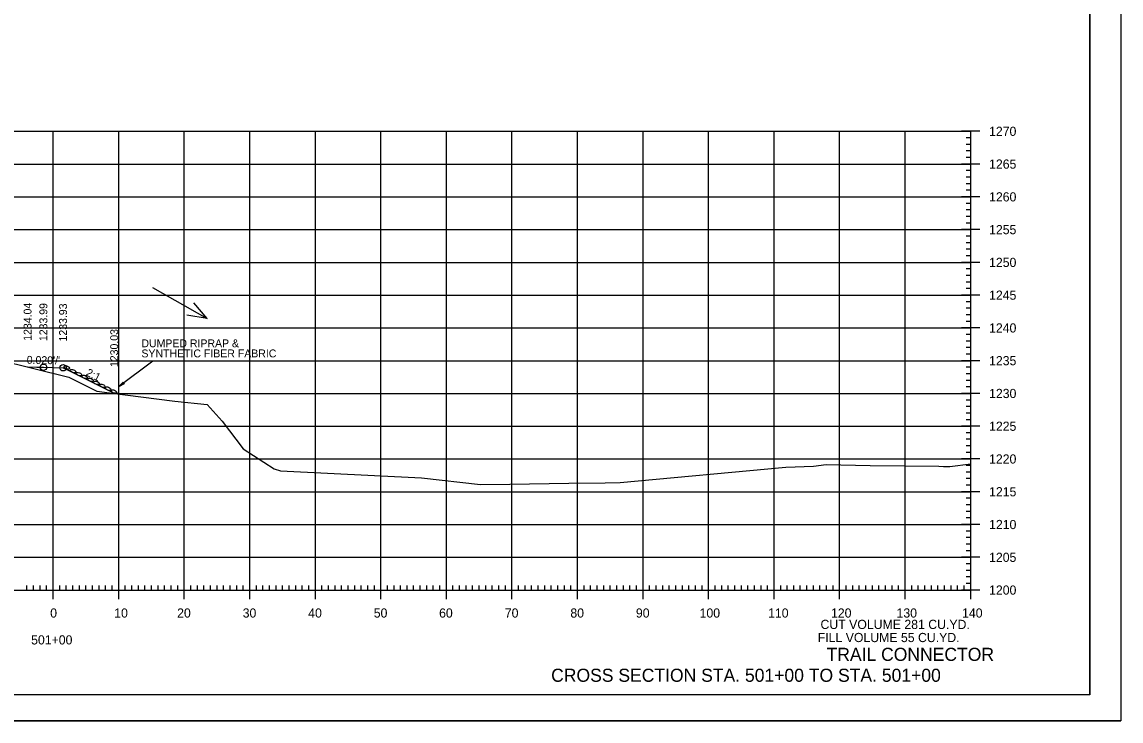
# Model space of a CAD drawing. Extents: x 1406028 to 1412453, y 321733 to 325986.
# Drawn here: x 1412285.5 to 1412453.2, y 322065 to 322171.7 of the extents above; entities that cross this region are included whole.
import ezdxf

# ---------------------------------------------------------------- set-up
doc = ezdxf.new("R2010")
doc.units = 0
for name, color, linetype in [('R_Axis', 7, 'Continuous'), ('R_Axis Annot', 7, 'Continuous'), ('R_Border', 7, 'Continuous'), ('R_Draft', 7, 'Continuous'), ('R_Exist Surface', 7, 'Continuous'), ('R_Fin Surface', 7, 'Continuous'), ('R_Fin Surface Annot', 7, 'Continuous'), ('R_Grid', 7, 'Continuous'), ('R_No Plot', 7, 'Continuous'), ('R_Water Annot', 7, 'Continuous')]:
    doc.layers.add(name, color=color, linetype=linetype)

msp = doc.modelspace()

# ---------------------------------------------------------------- linework, layer by layer
at = {"layer": 'R_Axis'}
for p, q in [((1412431.63, 322155.01), (1412428.83, 322155.01)), ((1412430.23, 322085.01), (1412430.23, 322155.01)), ((1412430.23, 322154.01), (1412429.53, 322154.01)), ((1412430.23, 322153.01), (1412429.53, 322153.01)), ((1412430.23, 322152.01), (1412429.53, 322152.01)), ((1412431.63, 322150.01), (1412428.83, 322150.01)), ((1412430.23, 322151.01), (1412429.53, 322151.01)), ((1412430.23, 322149.01), (1412429.53, 322149.01)), ((1412430.23, 322148.01), (1412429.53, 322148.01)), ((1412430.23, 322147.01), (1412429.53, 322147.01)), ((1412431.63, 322145.01), (1412428.83, 322145.01)), ((1412430.23, 322146.01), (1412429.53, 322146.01)), ((1412430.23, 322144.01), (1412429.53, 322144.01)), ((1412430.23, 322143.01), (1412429.53, 322143.01)), ((1412430.23, 322142.01), (1412429.53, 322142.01)), ((1412431.63, 322140.01), (1412428.83, 322140.01)), ((1412430.23, 322141.01), (1412429.53, 322141.01)), ((1412430.23, 322139.01), (1412429.53, 322139.01)), ((1412430.23, 322138.01), (1412429.53, 322138.01)), ((1412430.23, 322137.01), (1412429.53, 322137.01)), ((1412431.63, 322135.01), (1412428.83, 322135.01)), ((1412430.23, 322136.01), (1412429.53, 322136.01)), ((1412430.23, 322134.01), (1412429.53, 322134.01)), ((1412430.23, 322133.01), (1412429.53, 322133.01)), ((1412430.23, 322132.01), (1412429.53, 322132.01)), ((1412431.63, 322130.01), (1412428.83, 322130.01)), ((1412430.23, 322131.01), (1412429.53, 322131.01)), ((1412430.23, 322129.01), (1412429.53, 322129.01)), ((1412430.23, 322128.01), (1412429.53, 322128.01)), ((1412430.23, 322127.01), (1412429.53, 322127.01)), ((1412431.63, 322125.01), (1412428.83, 322125.01)), ((1412430.23, 322126.01), (1412429.53, 322126.01)), ((1412430.23, 322124.01), (1412429.53, 322124.01)), ((1412430.23, 322123.01), (1412429.53, 322123.01)), ((1412430.23, 322122.01), (1412429.53, 322122.01)), ((1412431.63, 322120.01), (1412428.83, 322120.01)), ((1412430.23, 322121.01), (1412429.53, 322121.01)), ((1412430.23, 322119.01), (1412429.53, 322119.01)), ((1412430.23, 322118.01), (1412429.53, 322118.01)), ((1412430.23, 322117.01), (1412429.53, 322117.01)), ((1412431.63, 322115.01), (1412428.83, 322115.01)), ((1412430.23, 322116.01), (1412429.53, 322116.01)), ((1412430.23, 322114.01), (1412429.53, 322114.01)), ((1412430.23, 322113.01), (1412429.53, 322113.01)), ((1412430.23, 322112.01), (1412429.53, 322112.01)), ((1412430.23, 322111.01), (1412429.53, 322111.01)), ((1412431.63, 322110.01), (1412428.83, 322110.01)), ((1412430.23, 322109.01), (1412429.53, 322109.01)), ((1412430.23, 322108.01), (1412429.53, 322108.01)), ((1412430.23, 322107.01), (1412429.53, 322107.01)), ((1412430.23, 322106.01), (1412429.53, 322106.01)), ((1412431.63, 322105.01), (1412428.83, 322105.01)), ((1412430.23, 322104.01), (1412429.53, 322104.01)), ((1412430.23, 322103.01), (1412429.53, 322103.01)), ((1412430.23, 322102.01), (1412429.53, 322102.01)), ((1412430.23, 322101.01), (1412429.53, 322101.01)), ((1412431.63, 322100.01), (1412428.83, 322100.01)), ((1412430.23, 322099.01), (1412429.53, 322099.01)), ((1412430.23, 322098.01), (1412429.53, 322098.01)), ((1412430.23, 322097.01), (1412429.53, 322097.01)), ((1412430.23, 322096.01), (1412429.53, 322096.01)), ((1412431.63, 322095.01), (1412428.83, 322095.01)), ((1412430.23, 322094.01), (1412429.53, 322094.01)), ((1412430.23, 322093.01), (1412429.53, 322093.01)), ((1412430.23, 322092.01), (1412429.53, 322092.01)), ((1412430.23, 322091.01), (1412429.53, 322091.01)), ((1412431.63, 322090.01), (1412428.83, 322090.01)), ((1412430.23, 322089.01), (1412429.53, 322089.01)), ((1412430.23, 322088.01), (1412429.53, 322088.01)), ((1412290.23, 322083.61), (1412290.23, 322086.41)), ((1412300.23, 322083.61), (1412300.23, 322086.41)), ((1412310.23, 322083.61), (1412310.23, 322086.41)), ((1412320.23, 322083.61), (1412320.23, 322086.41)), ((1412330.23, 322083.61), (1412330.23, 322086.41)), ((1412340.23, 322083.61), (1412340.23, 322086.41)), ((1412350.23, 322083.61), (1412350.23, 322086.41)), ((1412360.23, 322083.61), (1412360.23, 322086.41)), ((1412370.23, 322083.61), (1412370.23, 322086.41)), ((1412380.23, 322083.61), (1412380.23, 322086.41)), ((1412390.23, 322083.61), (1412390.23, 322086.41)), ((1412400.23, 322083.61), (1412400.23, 322086.41)), ((1412410.23, 322083.61), (1412410.23, 322086.41)), ((1412420.23, 322083.61), (1412420.23, 322086.41)), ((1412430.23, 322087.01), (1412429.53, 322087.01)), ((1412430.23, 322086.01), (1412429.53, 322086.01)), ((1412430.23, 322083.61), (1412430.23, 322086.41)), ((1412150.23, 322085.01), (1412430.23, 322085.01)), ((1412286.23, 322085.01), (1412286.23, 322085.71)), ((1412287.23, 322085.01), (1412287.23, 322085.71)), ((1412288.23, 322085.01), (1412288.23, 322085.71)), ((1412289.23, 322085.01), (1412289.23, 322085.71)), ((1412291.23, 322085.01), (1412291.23, 322085.71)), ((1412292.23, 322085.01), (1412292.23, 322085.71)), ((1412293.23, 322085.01), (1412293.23, 322085.71)), ((1412294.23, 322085.01), (1412294.23, 322085.71)), ((1412295.23, 322085.01), (1412295.23, 322085.71)), ((1412296.23, 322085.01), (1412296.23, 322085.71)), ((1412297.23, 322085.01), (1412297.23, 322085.71)), ((1412298.23, 322085.01), (1412298.23, 322085.71)), ((1412299.23, 322085.01), (1412299.23, 322085.71)), ((1412301.23, 322085.01), (1412301.23, 322085.71)), ((1412302.23, 322085.01), (1412302.23, 322085.71)), ((1412303.23, 322085.01), (1412303.23, 322085.71)), ((1412304.23, 322085.01), (1412304.23, 322085.71)), ((1412305.23, 322085.01), (1412305.23, 322085.71)), ((1412306.23, 322085.01), (1412306.23, 322085.71)), ((1412307.23, 322085.01), (1412307.23, 322085.71)), ((1412308.23, 322085.01), (1412308.23, 322085.71)), ((1412309.23, 322085.01), (1412309.23, 322085.71)), ((1412311.23, 322085.01), (1412311.23, 322085.71)), ((1412312.23, 322085.01), (1412312.23, 322085.71)), ((1412313.23, 322085.01), (1412313.23, 322085.71)), ((1412314.23, 322085.01), (1412314.23, 322085.71)), ((1412315.23, 322085.01), (1412315.23, 322085.71)), ((1412316.23, 322085.01), (1412316.23, 322085.71)), ((1412317.23, 322085.01), (1412317.23, 322085.71)), ((1412318.23, 322085.01), (1412318.23, 322085.71)), ((1412319.23, 322085.01), (1412319.23, 322085.71)), ((1412321.23, 322085.01), (1412321.23, 322085.71)), ((1412322.23, 322085.01), (1412322.23, 322085.71)), ((1412323.23, 322085.01), (1412323.23, 322085.71)), ((1412324.23, 322085.01), (1412324.23, 322085.71)), ((1412325.23, 322085.01), (1412325.23, 322085.71)), ((1412326.23, 322085.01), (1412326.23, 322085.71)), ((1412327.23, 322085.01), (1412327.23, 322085.71)), ((1412328.23, 322085.01), (1412328.23, 322085.71)), ((1412329.23, 322085.01), (1412329.23, 322085.71)), ((1412331.23, 322085.01), (1412331.23, 322085.71)), ((1412332.23, 322085.01), (1412332.23, 322085.71)), ((1412333.23, 322085.01), (1412333.23, 322085.71)), ((1412334.23, 322085.01), (1412334.23, 322085.71)), ((1412335.23, 322085.01), (1412335.23, 322085.71)), ((1412336.23, 322085.01), (1412336.23, 322085.71)), ((1412337.23, 322085.01), (1412337.23, 322085.71)), ((1412338.23, 322085.01), (1412338.23, 322085.71)), ((1412339.23, 322085.01), (1412339.23, 322085.71)), ((1412341.23, 322085.01), (1412341.23, 322085.71)), ((1412342.23, 322085.01), (1412342.23, 322085.71)), ((1412343.23, 322085.01), (1412343.23, 322085.71)), ((1412344.23, 322085.01), (1412344.23, 322085.71)), ((1412345.23, 322085.01), (1412345.23, 322085.71)), ((1412346.23, 322085.01), (1412346.23, 322085.71)), ((1412347.23, 322085.01), (1412347.23, 322085.71)), ((1412348.23, 322085.01), (1412348.23, 322085.71)), ((1412349.23, 322085.01), (1412349.23, 322085.71)), ((1412351.23, 322085.01), (1412351.23, 322085.71)), ((1412352.23, 322085.01), (1412352.23, 322085.71)), ((1412353.23, 322085.01), (1412353.23, 322085.71)), ((1412354.23, 322085.01), (1412354.23, 322085.71)), ((1412355.23, 322085.01), (1412355.23, 322085.71)), ((1412356.23, 322085.01), (1412356.23, 322085.71)), ((1412357.23, 322085.01), (1412357.23, 322085.71)), ((1412358.23, 322085.01), (1412358.23, 322085.71)), ((1412359.23, 322085.01), (1412359.23, 322085.71)), ((1412361.23, 322085.01), (1412361.23, 322085.71)), ((1412362.23, 322085.01), (1412362.23, 322085.71)), ((1412363.23, 322085.01), (1412363.23, 322085.71)), ((1412364.23, 322085.01), (1412364.23, 322085.71)), ((1412365.23, 322085.01), (1412365.23, 322085.71)), ((1412366.23, 322085.01), (1412366.23, 322085.71)), ((1412367.23, 322085.01), (1412367.23, 322085.71)), ((1412368.23, 322085.01), (1412368.23, 322085.71)), ((1412369.23, 322085.01), (1412369.23, 322085.71)), ((1412371.23, 322085.01), (1412371.23, 322085.71)), ((1412372.23, 322085.01), (1412372.23, 322085.71)), ((1412373.23, 322085.01), (1412373.23, 322085.71)), ((1412374.23, 322085.01), (1412374.23, 322085.71)), ((1412375.23, 322085.01), (1412375.23, 322085.71)), ((1412376.23, 322085.01), (1412376.23, 322085.71)), ((1412377.23, 322085.01), (1412377.23, 322085.71)), ((1412378.23, 322085.01), (1412378.23, 322085.71)), ((1412379.23, 322085.01), (1412379.23, 322085.71)), ((1412381.23, 322085.01), (1412381.23, 322085.71)), ((1412382.23, 322085.01), (1412382.23, 322085.71)), ((1412383.23, 322085.01), (1412383.23, 322085.71)), ((1412384.23, 322085.01), (1412384.23, 322085.71)), ((1412385.23, 322085.01), (1412385.23, 322085.71)), ((1412386.23, 322085.01), (1412386.23, 322085.71)), ((1412387.23, 322085.01), (1412387.23, 322085.71)), ((1412388.23, 322085.01), (1412388.23, 322085.71)), ((1412389.23, 322085.01), (1412389.23, 322085.71)), ((1412391.23, 322085.01), (1412391.23, 322085.71)), ((1412392.23, 322085.01), (1412392.23, 322085.71)), ((1412393.23, 322085.01), (1412393.23, 322085.71)), ((1412394.23, 322085.01), (1412394.23, 322085.71)), ((1412395.23, 322085.01), (1412395.23, 322085.71)), ((1412396.23, 322085.01), (1412396.23, 322085.71)), ((1412397.23, 322085.01), (1412397.23, 322085.71)), ((1412398.23, 322085.01), (1412398.23, 322085.71)), ((1412399.23, 322085.01), (1412399.23, 322085.71)), ((1412401.23, 322085.01), (1412401.23, 322085.71)), ((1412402.23, 322085.01), (1412402.23, 322085.71)), ((1412403.23, 322085.01), (1412403.23, 322085.71)), ((1412404.23, 322085.01), (1412404.23, 322085.71)), ((1412405.23, 322085.01), (1412405.23, 322085.71)), ((1412406.23, 322085.01), (1412406.23, 322085.71)), ((1412407.23, 322085.01), (1412407.23, 322085.71)), ((1412408.23, 322085.01), (1412408.23, 322085.71)), ((1412409.23, 322085.01), (1412409.23, 322085.71)), ((1412411.23, 322085.01), (1412411.23, 322085.71)), ((1412412.23, 322085.01), (1412412.23, 322085.71)), ((1412413.23, 322085.01), (1412413.23, 322085.71)), ((1412414.23, 322085.01), (1412414.23, 322085.71)), ((1412415.23, 322085.01), (1412415.23, 322085.71)), ((1412416.23, 322085.01), (1412416.23, 322085.71)), ((1412417.23, 322085.01), (1412417.23, 322085.71)), ((1412418.23, 322085.01), (1412418.23, 322085.71)), ((1412419.23, 322085.01), (1412419.23, 322085.71)), ((1412421.23, 322085.01), (1412421.23, 322085.71)), ((1412422.23, 322085.01), (1412422.23, 322085.71)), ((1412423.23, 322085.01), (1412423.23, 322085.71)), ((1412424.23, 322085.01), (1412424.23, 322085.71)), ((1412425.23, 322085.01), (1412425.23, 322085.71)), ((1412426.23, 322085.01), (1412426.23, 322085.71)), ((1412427.23, 322085.01), (1412427.23, 322085.71)), ((1412428.23, 322085.01), (1412428.23, 322085.71)), ((1412431.63, 322085.01), (1412428.83, 322085.01)), ((1412429.23, 322085.01), (1412429.23, 322085.71))]:
    msp.add_line(p, q, dxfattribs=at)
at = {"layer": 'R_Border'}
for q in [(1412448.41, 322274.47), (1412132.23, 322069.01)]:
    msp.add_line((1412448.41, 322069.01), q, dxfattribs=at)
at = {"layer": 'R_Draft'}
for p, q in [((1412305.41, 322119.94), (1412300.18, 322116.02)), ((1412300.89, 322116.74), (1412300.18, 322116.02)), ((1412301.07, 322116.5), (1412300.18, 322116.02)), ((1412300.9, 322116.72), (1412300.31, 322116.12)), ((1412301.05, 322116.52), (1412300.31, 322116.12)), ((1412300.92, 322116.7), (1412300.45, 322116.22)), ((1412301.04, 322116.54), (1412300.45, 322116.22)), ((1412300.93, 322116.68), (1412300.58, 322116.32)), ((1412301.02, 322116.56), (1412300.58, 322116.32)), ((1412300.95, 322116.66), (1412300.72, 322116.42)), ((1412301.01, 322116.58), (1412300.72, 322116.42)), ((1412300.97, 322116.64), (1412300.85, 322116.52)), ((1412300.99, 322116.6), (1412300.85, 322116.52)), ((1412300.89, 322116.74), (1412301.07, 322116.5))]:
    msp.add_line(p, q, dxfattribs=at)
for centre in [(1412292.32, 322118.96), (1412293.25, 322118.42), (1412294.14, 322117.97), (1412295.04, 322117.53), (1412295.93, 322117.08), (1412296.83, 322116.63), (1412297.72, 322116.19), (1412298.61, 322115.74), (1412299.51, 322115.29)]:
    msp.add_ellipse(centre, major_axis=(0.409, -0.156), ratio=0.517889, dxfattribs=at)
at = {"layer": 'R_Exist Surface'}
msp.add_lwpolyline([(1412281.68, 322120.19), (1412292.6, 322117.5), (1412296.88, 322115.35), (1412298.81, 322115.13), (1412308.77, 322113.85), (1412313.72, 322113.35), (1412316, 322110.76), (1412319.21, 322106.56), (1412323.97, 322103.5), (1412324.89, 322103.22), (1412346.45, 322102.11), (1412355.44, 322101.1), (1412359.88, 322101.16), (1412368.91, 322101.31), (1412374.44, 322101.39), (1412376.73, 322101.43), (1412402.01, 322103.77), (1412406.24, 322103.91), (1412408.15, 322104.16), (1412414.88, 322104.01), (1412425.34, 322103.9), (1412426.1, 322103.84), (1412427.04, 322103.88), (1412430.23, 322104.27)], dxfattribs=at)
at = {"layer": 'R_Fin Surface'}
msp.add_lwpolyline([(1412286.32, 322119.05), (1412287.73, 322119.02), (1412288.73, 322119), (1412291.73, 322118.94), (1412292.73, 322118.44), (1412299.53, 322115.04)], dxfattribs=at)
at = {"layer": 'R_Grid'}
for p, q in [((1412150.23, 322155.01), (1412430.23, 322155.01)), ((1412290.23, 322085.01), (1412290.23, 322155.01)), ((1412300.23, 322085.01), (1412300.23, 322155.01)), ((1412310.23, 322085.01), (1412310.23, 322155.01)), ((1412320.23, 322085.01), (1412320.23, 322155.01)), ((1412330.23, 322085.01), (1412330.23, 322155.01)), ((1412340.23, 322085.01), (1412340.23, 322155.01)), ((1412350.23, 322085.01), (1412350.23, 322155.01)), ((1412360.23, 322085.01), (1412360.23, 322155.01)), ((1412370.23, 322085.01), (1412370.23, 322155.01)), ((1412380.23, 322085.01), (1412380.23, 322155.01)), ((1412390.23, 322085.01), (1412390.23, 322155.01)), ((1412400.23, 322085.01), (1412400.23, 322155.01)), ((1412410.23, 322085.01), (1412410.23, 322155.01)), ((1412420.23, 322085.01), (1412420.23, 322155.01)), ((1412430.23, 322085.01), (1412430.23, 322155.01)), ((1412150.23, 322150.01), (1412430.23, 322150.01)), ((1412150.23, 322145.01), (1412430.23, 322145.01)), ((1412150.23, 322140.01), (1412430.23, 322140.01)), ((1412150.23, 322135.01), (1412430.23, 322135.01)), ((1412150.23, 322130.01), (1412430.23, 322130.01)), ((1412150.23, 322125.01), (1412430.23, 322125.01)), ((1412150.23, 322120.01), (1412430.23, 322120.01)), ((1412150.23, 322115.01), (1412430.23, 322115.01)), ((1412150.23, 322110.01), (1412430.23, 322110.01)), ((1412150.23, 322105.01), (1412430.23, 322105.01)), ((1412150.23, 322100.01), (1412430.23, 322100.01)), ((1412150.23, 322095.01), (1412430.23, 322095.01)), ((1412150.23, 322090.01), (1412430.23, 322090.01)), ((1412150.23, 322085.01), (1412430.23, 322085.01))]:
    msp.add_line(p, q, dxfattribs=at)
at = {"layer": 'R_No Plot'}
msp.add_line((1412119.83, 322065.03), (1412453.16, 322065.03), dxfattribs=at)
for points in [[(1412119.82, 322278.36), (1412453.16, 322278.36), (1412453.16, 322065.03), (1412119.82, 322065.03)], [(1412366.15, 322274.47), (1412385.77, 322274.47), (1412385.77, 322264.59), (1412401.88, 322264.59), (1412425.08, 322264.59), (1412425.2, 322236.43), (1412448.41, 322236.43), (1412448.41, 322069.01), (1412132.23, 322069.01), (1412132.23, 322274.47)]]:
    msp.add_lwpolyline(points, close=True, dxfattribs=at)
for centre in [(1412288.73, 322119), (1412291.73, 322118.94)]:
    msp.add_circle(centre, 0.5, dxfattribs=at)
at = {"layer": 'R_Water Annot'}
for p, q in [((1412305.39, 322131.2), (1412313.71, 322126.46)), ((1412313.71, 322126.46), (1412311.7, 322128.84)), ((1412313.71, 322126.46), (1412310.64, 322126.98))]:
    msp.add_line(p, q, dxfattribs=at)

# ---------------------------------------------------------------- texts
at = {"layer": 'R_Axis Annot'}
for s, p in [('1270', (1412433.03, 322154.31)), ('1265', (1412433.03, 322149.31)), ('1260', (1412433.03, 322144.31)), ('1255', (1412433.03, 322139.31)), ('1250', (1412433.03, 322134.31)), ('1245', (1412433.03, 322129.31)), ('1240', (1412433.03, 322124.31)), ('1235', (1412433.03, 322119.31)), ('1230', (1412433.03, 322114.31)), ('1225', (1412433.03, 322109.31)), ('1220', (1412433.03, 322104.31)), ('1215', (1412433.03, 322099.31)), ('1210', (1412433.03, 322094.31)), ('1205', (1412433.03, 322089.31)), ('1200', (1412433.03, 322084.31)), ('0', (1412289.77, 322080.81)), ('10', (1412299.54, 322080.81)), ('20', (1412309.14, 322080.81)), ('30', (1412319.14, 322080.81)), ('40', (1412329.14, 322080.81)), ('50', (1412339.14, 322080.81)), ('60', (1412349.11, 322080.81)), ('70', (1412359.14, 322080.81)), ('80', (1412369.14, 322080.81)), ('90', (1412379.14, 322080.81)), ('100', (1412388.86, 322080.81)), ('110', (1412399.31, 322080.81)), ('120', (1412408.91, 322080.81)), ('130', (1412418.91, 322080.81)), ('140', (1412428.91, 322080.81)), ('CUT VOLUME 281 CU.YD.', (1412407.31, 322079.07)), ('501+00', (1412286.86, 322076.71)), ('FILL VOLUME 55 CU.YD.', (1412406.89, 322077.07))]:
    msp.add_text(s, height=1.4, dxfattribs=at).set_placement(p)
at = {"layer": 'R_Draft'}
for s, height, p in [('DUMPED RIPRAP &', 1.2, (1412303.69, 322122.06)), ('SYNTHETIC FIBER FABRIC', 1.2, (1412303.69, 322120.52)), ('TRAIL CONNECTOR', 2, (1412408.23, 322074.2)), ('CROSS SECTION STA. 501+00 TO STA. 501+00', 2, (1412366.21, 322071.01))]:
    msp.add_text(s, height=height, dxfattribs=at).set_placement(p)
at = {"layer": 'R_Fin Surface Annot'}
for s, rotation, p in [('1234.04', 90, (1412286.92, 322123.05)), ('1233.99', 90, (1412289.33, 322123)), ('1233.93', 90, (1412292.33, 322122.94)), ('1230.03', 90, (1412300.13, 322119.04)), ("0.020'/'", 358.8542, (1412286.18, 322119.55)), ('2:1', 333.4349, (1412295.11, 322117.81))]:
    msp.add_text(s, height=1.2, rotation=rotation, dxfattribs=at).set_placement(p)

doc.saveas('drawing.dxf')
